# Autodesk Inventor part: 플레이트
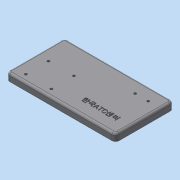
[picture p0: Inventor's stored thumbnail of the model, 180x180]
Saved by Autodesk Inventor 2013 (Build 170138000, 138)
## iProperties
Created: 2018-01
Part Number: 플레이트
Material: 알루미늄 6061
Document SubType Name: Modeling
Designer: mduedu
Density: 2.71 g/cm^3
Mass: 319.562 g
Surface Area: 287.617 cm^2
Volume: 117.92 cm^3
Author: mduedu
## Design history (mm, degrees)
sketch "스케치1"
  geometry: L1 (75, 40)-(-75, 40); L2 (-75, 40)-(-75, -40); L3 (-75, -40)-(75, -40); L4 (75, -40)-(75, 40); L5 (75, 40)-(-75, -40); L6 (-75, 40)-(75, -40); 1 further point
  constraints: 12 end point, 2 midpoint, 2 parallel, 1 horizontal, 1 perpendicular
  dimensions: "d0" = 150 distance of L3.end L2.end; "d1" = 80 distance of L2.end L1.end
extrude "돌출1" new body sketch "스케치1" distance "d2" = 10; taper "d3" = 0 deg
fillet "모깎기1" dims "d4" = 5
fillet "모깎기2" dims "d5" = 3
sketch "스케치2"
  geometry: L1 (-70, 40)-(70, 40) reference; L2 (-75, -35)-(-75, 35) reference; 5 further points
  constraints: 2 horizontal alignment, 2 vertical alignment
  dimensions: "d6" = 10 distance from line of point (-58, 30) L1; "d7" = 35 distance of point (-23, 30) point (-58, 30); "d8" = 31 distance of point (-58, -1) point (-58, 30); "d9" = 17 distance from line of point (-58, 30) L2
sketch "스케치3"
  geometry: 4 further points
  constraints: 4 other
hole "구멍1" sketch "스케치3" at (-23, 30), (-58, -1), (-23, -1), (-58, 30) diameter "d10" = 3.4; stored, may be unused: countersink angle "d14" = 90 deg, drill point angle "d16" = 0 deg; dims "d11" = 6, "d12" = 6.5, "d13" = 3.4, "d15" = 8
sketch "스케치4"
  geometry: L1 (75, 35)-(75, -35) reference; L2 (70, -40)-(-70, -40) reference; 3 further points
  constraints: 1 horizontal alignment
  dimensions: "d17" = 17 distance from line of point (58, -22) L1; "d18" = 18 distance of point (40, -22) point (58, -22); "d19" = 18 distance from line of point (58, -22) L2
sketch "스케치5"
  geometry: 2 further points
  constraints: 2 other
hole "구멍2" sketch "스케치5" at (40, -22), (58, -22) diameter "d20" = 3.4; stored, may be unused: countersink angle "d24" = 90 deg, drill point angle "d26" = 0 deg; dims "d21" = 6, "d22" = 6.5, "d23" = 3.4, "d25" = 8
sketch "스케치6"
  geometry: L1 (75, -35)-(75, 35) reference; L2 (-70, -40)-(70, -40) reference; 2 further points
  constraints: 1 other
  dimensions: "d27" = 40 distance from line of point (35, -20) L1; "d28" = 20 distance from line of point (35, -20) L2
feature "엠보싱1" sketch "스케치6" dims "d0" = 150, "d29" = 0.5, "d30" = 0
node "솔리드1"
